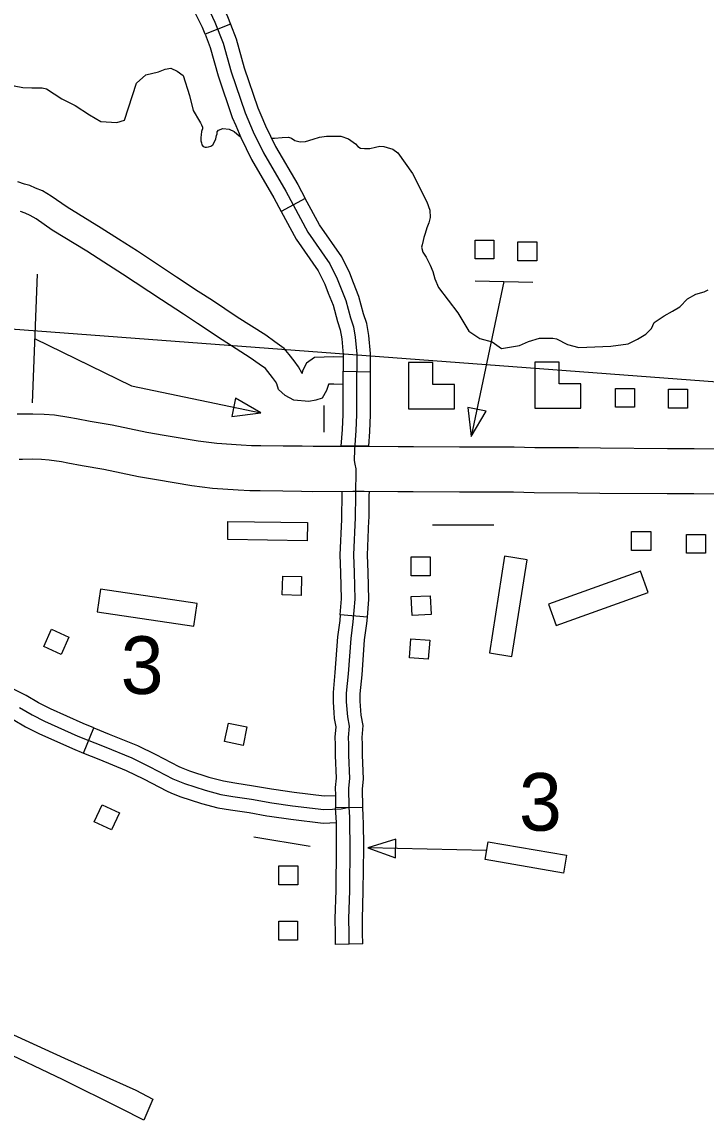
# Model space of a CAD drawing. Extents: x 61396 to 64680, y 55472 to 57605.
# Drawn here: x 62308.8 to 62426.4, y 55934.9 to 56123.6 of the extents above; entities that cross this region are included whole.
import ezdxf

# ---------------------------------------------------------------- set-up
doc = ezdxf.new("R2010")
doc.units = 0
for name, color, linetype in [('15', 7, 'Continuous'), ('31', 7, 'Continuous'), ('35', 7, 'Continuous'), ('46', 7, 'Continuous'), ('56', 7, 'Continuous'), ('57', 7, 'Continuous'), ('58', 7, 'Continuous'), ('Default', 7, 'Continuous')]:
    doc.layers.add(name, color=color, linetype=linetype)

msp = doc.modelspace()

# ---------------------------------------------------------------- linework, layer by layer
at = {"layer": '15'}
for points in [[(62308.01, 56056.27), (62308.83, 56056.27), (62310.69, 56056.29), (62312.62, 56056.26), (62314.42, 56056.09), (62316.89, 56055.73), (62318.17, 56055.48), (62320.53, 56055.04), (62324.31, 56054.42), (62330.3, 56053.15), (62333.27, 56052.65), (62339.11, 56051.65), (62342.29, 56051.27), (62346.52, 56050.99), (62348.3, 56050.87), (62349.88, 56050.85), (62353.73, 56050.8), (62356.99, 56050.77), (62358.87, 56050.72), (62365.66, 56050.75), (62367.7, 56050.75), (62373.52, 56050.7), (62376.13, 56050.67), (62384.04, 56050.62), (62387.49, 56050.64), (62393.45, 56050.64), (62397.02, 56050.52), (62404.49, 56050.49), (62408.26, 56050.42), (62419.8, 56050.34), (62424.38, 56050.34), (62432.67, 56050.29)], [(62432.65, 56042.48), (62424.35, 56042.53), (62419.77, 56042.53), (62408.16, 56042.6), (62404.4, 56042.68), (62396.86, 56042.71), (62393.31, 56042.83), (62387.51, 56042.83), (62384.04, 56042.81), (62376.07, 56042.86), (62373.45, 56042.88), (62367.66, 56042.93), (62365.68, 56042.93), (62358.78, 56042.91), (62356.85, 56042.96), (62353.65, 56042.99), (62349.77, 56043.04), (62347.98, 56043.06), (62346, 56043.2), (62341.58, 56043.48), (62337.99, 56043.91), (62331.97, 56044.95), (62328.84, 56045.47), (62322.87, 56046.74), (62319.17, 56047.34), (62316.7, 56047.81), (62315.59, 56048.02), (62313.48, 56048.33), (62312.18, 56048.46), (62310.69, 56048.48), (62308.89, 56048.45), (62308.33, 56048.45)]]:
    msp.add_lwpolyline(points, dxfattribs=at)
at = {"layer": '31'}
for p, q in [((62344.65, 56123.22), (62340.29, 56121.51)), ((62357.51, 56093.28), (62353.38, 56091.07)), ((62364.06, 56063.61), (62368.75, 56063.53)), ((62368.43, 56050.74), (62363.72, 56050.74)), ((62368.2, 56021.36), (62363.53, 56021.76)), ((62319.42, 55997.99), (62321.17, 56002.34)), ((62362.74, 55988.63), (62367.43, 55988.72)), ((62367.43, 55988.72), (62367.43, 55988.72)), ((62367.42, 55965.2), (62362.73, 55965.13))]:
    msp.add_line(p, q, dxfattribs=at)
for points in [[(62333.64, 56136.67), (62338.22, 56132.83), (62341.42, 56129.46), (62342.2, 56128.31), (62342.87, 56127.15), (62344.13, 56124.56), (62344.65, 56123.22)], [(62340.29, 56121.51), (62339.83, 56122.69), (62338.73, 56124.95), (62338.23, 56125.81), (62337.76, 56126.51), (62335.01, 56129.41), (62330.63, 56133.08)], [(62340.8, 56126.05), (62341.98, 56123.62), (62343.4, 56119.98), (62344.78, 56115.08), (62347.17, 56108.04), (62348.56, 56104.77), (62350.36, 56101.12), (62354.17, 56094.55), (62357.94, 56087.51), (62361.76, 56082.06), (62363.01, 56079.51), (62364.52, 56075.74), (62365.32, 56072.8), (62365.82, 56071.25), (62366.11, 56069.45), (62366.36, 56066.56), (62366.41, 56063.57)], [(62344.65, 56123.22), (62345.63, 56120.72), (62347.02, 56115.77), (62349.37, 56108.87), (62349.88, 56107.65)], [(62340.29, 56121.51), (62341.18, 56119.23), (62342.55, 56114.38), (62344.98, 56107.2), (62345.56, 56105.83)], [(62349.88, 56107.65), (62350.69, 56105.75), (62352.42, 56102.23), (62356.22, 56095.69), (62357.51, 56093.28)], [(62345.56, 56105.83), (62346.42, 56103.79), (62348.29, 56100.02), (62352.12, 56093.41), (62353.38, 56091.07)], [(62365.82, 56078.79), (62365.16, 56080.46), (62363.78, 56083.26), (62359.94, 56088.74), (62357.51, 56093.28)], [(62353.38, 56091.07), (62355.94, 56086.28), (62359.73, 56080.87), (62360.87, 56078.55), (62361.47, 56077.05)], [(62368.75, 56063.53), (62368.71, 56066.68), (62368.44, 56069.74), (62368.1, 56071.81), (62367.56, 56073.47), (62366.75, 56076.48), (62365.82, 56078.79)], [(62361.47, 56077.05), (62362.29, 56074.99), (62363.07, 56072.13), (62363.54, 56070.7), (62363.79, 56069.16), (62364.02, 56066.44), (62364.06, 56063.61)], [(62363.72, 56050.74), (62363.95, 56053.57), (62364.06, 56056.15), (62364.02, 56058), (62364.02, 56061.16), (62364.06, 56063.33), (62364.06, 56063.61)], [(62366.29, 56046.84), (62366.1, 56047.65), (62366.03, 56047.94), (62365.99, 56048.33), (62366.02, 56050.11), (62366.29, 56053.42), (62366.4, 56056.12), (62366.37, 56058.03), (62366.37, 56061.14), (62366.41, 56063.57)], [(62368.43, 56050.74), (62368.63, 56053.28), (62368.75, 56056.1), (62368.71, 56058.05), (62368.71, 56061.12), (62368.75, 56063.25), (62368.75, 56063.53)], [(62365.08, 55988.68), (62365.02, 55991.95), (62365.21, 55993.62), (62365.02, 55997.64), (62365.02, 55999.5), (62364.97, 56000.69), (62365.11, 56002.6), (62364.82, 56004.23), (62364.63, 56006.81), (62364.63, 56008.29), (62364.97, 56011.64), (62365.4, 56017.7), (62365.78, 56020.52), (62366.11, 56024.44), (62365.97, 56029.03), (62365.88, 56032.04), (62366.14, 56038.47), (62366.19, 56042.27), (62366.29, 56046.84)], [(62363.78, 56038.14), (62363.8, 56038.53), (62363.84, 56042.31), (62363.86, 56042.93)], [(62368.46, 56037.94), (62368.48, 56038.4), (62368.53, 56042.22), (62368.55, 56042.93)], [(62363.53, 56021.76), (62363.77, 56024.51), (62363.63, 56028.96), (62363.53, 56032.05), (62363.78, 56038.14)], [(62368.2, 56021.36), (62368.46, 56024.38), (62368.31, 56029.1), (62368.22, 56032.03), (62368.46, 56037.94)], [(62363.53, 56021.76), (62363.45, 56020.78), (62363.07, 56017.95), (62362.63, 56011.84), (62362.29, 56008.41), (62362.29, 56006.72), (62362.42, 56004.95)], [(62367.1, 56005.3), (62366.98, 56006.9), (62366.98, 56008.17), (62367.3, 56011.44), (62367.73, 56017.46), (62368.11, 56020.27), (62368.2, 56021.36)], [(62321.17, 56002.34), (62319.35, 56003.07), (62313.72, 56005.61), (62311.67, 56006.65), (62309.54, 56007.89), (62307.27, 56009.04), (62306.42, 56009.43)], [(62304.46, 56005.17), (62305.24, 56004.82), (62307.29, 56003.78), (62309.43, 56002.53), (62311.7, 56001.38), (62317.51, 55998.76), (62319.42, 55997.99)], [(62308.41, 56005.84), (62310.55, 56004.59), (62312.71, 56003.49), (62318.43, 56000.92), (62322.93, 55999.1), (62327.69, 55997.15), (62330.77, 55995.66), (62334.77, 55993.58), (62336.78, 55992.75), (62340.31, 55991.6), (62342.99, 55990.9), (62345.05, 55990.56), (62348.25, 55990.07), (62351.76, 55989.47), (62355.33, 55988.95), (62360.69, 55988.3), (62363.69, 55988.41), (62365.08, 55988.68)], [(62362.42, 56004.95), (62362.5, 56003.94), (62362.75, 56002.49), (62362.62, 56000.73), (62362.67, 55999.45), (62362.67, 55997.58), (62362.86, 55993.7), (62362.67, 55992.06), (62362.7, 55990.72)], [(62367.43, 55988.72), (62367.36, 55991.84), (62367.56, 55993.54), (62367.36, 55997.69), (62367.36, 55999.55), (62367.32, 56000.65), (62367.47, 56002.72), (62367.15, 56004.52), (62367.1, 56005.3)], [(62321.17, 56002.34), (62323.82, 56001.27), (62328.65, 55999.29), (62331.82, 55997.76), (62335.76, 55995.71), (62336.21, 55995.52)], [(62319.42, 55997.99), (62322.05, 55996.93), (62326.74, 55995), (62329.72, 55993.57), (62333.78, 55991.46), (62334.41, 55991.19)], [(62336.21, 55995.52), (62337.59, 55994.95), (62340.97, 55993.85), (62343.48, 55993.2), (62345.42, 55992.88), (62348.63, 55992.38), (62351.7, 55991.86)], [(62351.7, 55991.86), (62352.13, 55991.79), (62355.64, 55991.27), (62360.79, 55990.65), (62362.7, 55990.72)], [(62334.41, 55991.19), (62335.96, 55990.55), (62339.66, 55989.35), (62342.51, 55988.61), (62344.68, 55988.25), (62347.88, 55987.76), (62350.92, 55987.24)], [(62362.7, 55990.72), (62362.74, 55988.63)], [(62362.87, 55986.04), (62362.82, 55986.9), (62362.74, 55988.57)], [(62365.08, 55965.17), (62365.05, 55967.03), (62365.02, 55969.49), (62365.16, 55974.36), (62365.24, 55982.03), (62365.21, 55985.89), (62365.16, 55987.01), (62365.08, 55988.68)], [(62367.58, 55981.64), (62367.58, 55982.02), (62367.56, 55985.95), (62367.5, 55987.12), (62367.42, 55988.78)], [(62350.92, 55987.24), (62351.4, 55987.16), (62355.02, 55986.63), (62360.59, 55985.95), (62362.87, 55986.04)], [(62362.89, 55981.69), (62362.9, 55982.03), (62362.87, 55986.04)], [(62362.73, 55965.13), (62362.7, 55967), (62362.68, 55969.51), (62362.81, 55974.41), (62362.89, 55981.69)], [(62367.42, 55965.2), (62367.39, 55967.06), (62367.36, 55969.47), (62367.5, 55974.32), (62367.58, 55981.64)]]:
    msp.add_lwpolyline(points, dxfattribs=at)
at = {"layer": '35'}
for points in [[(62299.41, 56123.93), (62299.41, 56123.04), (62298.76, 56122.51), (62297.74, 56122.47), (62296.6, 56122.47), (62295.71, 56122.06), (62295.26, 56121.37), (62295.43, 56120.07), (62295.75, 56117.96), (62296.69, 56117.35), (62298.43, 56116.99), (62300.18, 56115.93), (62301.68, 56115.69), (62303.14, 56114.39), (62305.09, 56113.53), (62306.27, 56113.09), (62307.45, 56112.64), (62308.95, 56112.36), (62310.49, 56112.28), (62312.28, 56112.32), (62313.05, 56112.15)], [(62313.05, 56112.15), (62315.64, 56110.41), (62317.98, 56109.3), (62320.44, 56107.65), (62322.38, 56106.52), (62325.14, 56106.35), (62326.47, 56106.75), (62328.51, 56113.11), (62330.09, 56114.52), (62332.28, 56115.07), (62333.46, 56115.54), (62334.41, 56115.7), (62335.5, 56115.15), (62336.53, 56114.44), (62337.63, 56110.99), (62338.25, 56108.4), (62339.36, 56106.59), (62339.52, 56106.31), (62339.69, 56105.94), (62339.83, 56105.54), (62339.84, 56105.29), (62339.75, 56104.97), (62339.66, 56104.78), (62339.65, 56104.21), (62339.57, 56103.8), (62339.59, 56103.21), (62339.66, 56102.83), (62339.73, 56102.52), (62339.99, 56102.25), (62340.31, 56102.13), (62340.56, 56102.14)], [(62340.56, 56102.14), (62340.9, 56102.15), (62341.31, 56102.29), (62341.61, 56102.49), (62341.91, 56103.03), (62342.14, 56103.54), (62342.25, 56104.14), (62342.37, 56104.43), (62342.39, 56104.74), (62342.6, 56105.06), (62343.34, 56105.3), (62344.41, 56105.21), (62345.27, 56104.83), (62346.14, 56104.04), (62346.32, 56103.97)], [(62351.76, 56103.65), (62352.23, 56103.67), (62353.57, 56103.75), (62354.63, 56103.81), (62355.17, 56103.67), (62355.72, 56103.25), (62356.66, 56103.03), (62357.54, 56103.09), (62358.9, 56103.51), (62359.96, 56103.83), (62361.17, 56104.02), (62363.65, 56104.01), (62364.95, 56103.55), (62366.13, 56102.71), (62366.55, 56102.22), (62367, 56101.95), (62367.69, 56101.88), (62368.6, 56101.87), (62369.6, 56102.09), (62370.37, 56102.28), (62371.03, 56102.2), (62371.63, 56102.03), (62372.55, 56101.78), (62373.41, 56101.15), (62375.97, 56097.56), (62378.4, 56092.74), (62378.91, 56091.31), (62378.99, 56090), (62378.76, 56089.11), (62378.44, 56088.25), (62378.13, 56087.27), (62377.93, 56086.61), (62377.79, 56086.07), (62377.6, 56085.31), (62377.51, 56084.93), (62377.73, 56084.09), (62378.32, 56083.2), (62378.99, 56081.81), (62379.43, 56080.75), (62379.78, 56079.51), (62380.42, 56078.02), (62383.76, 56073.63), (62385.66, 56070.48), (62387.52, 56069.22), (62389.67, 56068.67), (62391.28, 56067.52), (62394.38, 56068.04), (62395.89, 56068.7), (62397.79, 56069.27), (62400.07, 56069.27), (62400.73, 56069.18), (62402.63, 56068.23), (62404.53, 56067.66), (62410.03, 56067.94), (62413.04, 56068.3), (62414.67, 56069.14), (62416.06, 56070), (62417.06, 56070.97), (62417.53, 56071.96), (62419.22, 56073.14), (62420.64, 56073.91), (62421.9, 56074.67)], [(62421.9, 56074.67), (62423.23, 56076.06), (62424.65, 56076.86), (62426.11, 56077.28), (62426.82, 56077.62)]]:
    msp.add_lwpolyline(points, dxfattribs=at)
at = {"layer": '46'}
for points in [[(62364.03, 56066.02), (62362.44, 56066.1), (62359.1, 56065.99), (62357.76, 56064.99), (62357.04, 56063.67), (62357, 56063.23), (62356.97, 56063.23), (62356.37, 56064.38), (62355.6, 56065.4), (62354.75, 56066.47), (62353.91, 56067.54), (62352.3, 56068.64), (62350.72, 56069.79), (62345.82, 56072.92), (62341.58, 56075.77), (62339.1, 56077.33), (62335.39, 56079.78), (62328.67, 56084.24), (62325.43, 56086.3), (62322.43, 56088.2), (62316.57, 56091.78), (62313.81, 56093.7), (62312.37, 56094.59), (62311.15, 56095.08), (62310.18, 56095.5), (62309.25, 56095.78), (62308.1, 56096.16)], [(62364.03, 56061.33), (62362.41, 56061.41), (62361.51, 56061.38), (62361.51, 56061.31), (62361.2, 56060.3), (62360.45, 56059.01), (62359.32, 56058.63), (62358.12, 56058.41), (62355.54, 56058.65), (62354.07, 56059.43), (62352.92, 56060.48), (62352.62, 56061.43), (62352.39, 56061.87), (62351.9, 56062.53), (62351.08, 56063.55), (62350.67, 56064.07), (62349.59, 56064.81), (62348.07, 56065.92), (62343.25, 56069), (62339.02, 56071.84), (62336.56, 56073.39), (62332.81, 56075.88), (62326.12, 56080.31), (62322.91, 56082.35), (62319.96, 56084.22), (62314, 56087.85), (62311.23, 56089.78), (62310.24, 56090.39), (62309.36, 56090.75), (62308.58, 56091.08)]]:
    msp.add_lwpolyline(points, dxfattribs=at)
at = {"layer": '56'}
for points in [[(62386.71, 56082.9), (62386.71, 56086.15), (62389.97, 56086.15), (62389.97, 56082.9)], [(62394.06, 56082.57), (62394.06, 56085.82), (62397.32, 56085.82), (62397.32, 56082.57)], [(62410.87, 56057.42), (62410.87, 56060.67), (62414.13, 56060.67), (62414.13, 56057.42)], [(62419.96, 56057.26), (62419.96, 56060.51), (62423.22, 56060.51), (62423.22, 56057.26)], [(62388.62, 56056.73), (62385.5, 56057.38), (62386.07, 56052.38)], [(62344.18, 56034.67), (62344.22, 56037.79), (62357.89, 56037.59), (62357.85, 56034.47)], [(62413.64, 56032.8), (62413.64, 56036.05), (62416.91, 56036.05), (62416.91, 56032.8)], [(62423.08, 56032.32), (62423.08, 56035.57), (62426.34, 56035.57), (62426.34, 56032.32)], [(62375.72, 56028.46), (62375.72, 56031.71), (62378.99, 56031.71), (62378.99, 56028.46)], [(62353.57, 56025.17), (62353.64, 56028.42), (62356.9, 56028.35), (62356.83, 56025.1)], [(62375.88, 56021.66), (62375.75, 56024.91), (62379.01, 56025.04), (62379.14, 56021.79)], [(62312.56, 56016.29), (62313.88, 56019.26), (62316.86, 56017.94), (62315.54, 56014.96)], [(62375.43, 56014.39), (62375.69, 56017.64), (62378.94, 56017.37), (62378.68, 56014.13)], [(62343.64, 55999.98), (62344.31, 56003.16), (62347.5, 56002.49), (62346.84, 55999.31)], [(62321.24, 55986.18), (62322.63, 55989.11), (62325.58, 55987.71), (62324.18, 55984.78)], [(62373.05, 55979.99), (62373.12, 55983.18), (62368.3, 55981.69)], [(62388.43, 55979.69), (62388.96, 55982.77), (62402.43, 55980.45), (62401.9, 55977.37)], [(62352.96, 55975.36), (62352.96, 55978.61), (62356.22, 55978.61), (62356.22, 55975.36)], [(62352.95, 55965.85), (62352.95, 55969.1), (62356.21, 55969.1), (62356.21, 55965.85)]]:
    msp.add_lwpolyline(points, close=True, dxfattribs=at)
for points in [[(62391.69, 56079.02), (62386.07, 56052.38)], [(62386.76, 56079.13), (62396.62, 56078.9)], [(62379.38, 56037.23), (62389.94, 56037.23)], [(62348.67, 55983.61), (62358.34, 55982.02)], [(62388.69, 55981.23), (62368.3, 55981.69)]]:
    msp.add_lwpolyline(points, dxfattribs=at)
at = {"layer": '57'}
for p, q in [((62391.8, 56031.81), (62389.18, 56015.22)), ((62395.66, 56031.2), (62391.8, 56031.81)), ((62393.04, 56014.61), (62395.66, 56031.2)), ((62415.14, 56029.27), (62399.33, 56023.59)), ((62416.46, 56025.59), (62415.14, 56029.27)), ((62322.29, 56026.14), (62321.72, 56022.28)), ((62338.91, 56023.7), (62322.29, 56026.14)), ((62400.65, 56019.92), (62416.46, 56025.59)), ((62321.72, 56022.28), (62338.34, 56019.83)), ((62338.34, 56019.83), (62338.91, 56023.7)), ((62399.33, 56023.59), (62400.65, 56019.92)), ((62389.18, 56015.22), (62393.04, 56014.61)), ((62300.7, 55952.65), (62316.12, 55945.56)), ((62315.92, 55941.84), (62300.26, 55949.28)), ((62316.12, 55945.56), (62328.4, 55940.08)), ((62325.81, 55936.94), (62315.92, 55941.84)), ((62328.4, 55940.08), (62331.34, 55938.51)), ((62331.34, 55938.51), (62329.77, 55934.94)), ((62329.77, 55934.94), (62325.81, 55936.94))]:
    msp.add_line(p, q, dxfattribs=at)
msp.add_lwpolyline([(62310.99, 56069.22), (62327.67, 56061.08), (62349.89, 56056.44)], dxfattribs=at)
msp.add_lwpolyline([(62345.53, 56058.98), (62344.88, 56055.86), (62349.89, 56056.44)], close=True, dxfattribs=at)
at = {"layer": '58'}
for points in [[(62311.45, 56080.27), (62310.54, 56058.16)], [(62360.69, 56057.71), (62360.69, 56053.15)]]:
    msp.add_lwpolyline(points, dxfattribs=at)
for points in [[(62375.25, 56057.15), (62383.19, 56057.15), (62383.19, 56061.34), (62379.44, 56061.34), (62379.44, 56065.09), (62375.25, 56065.09)], [(62396.98, 56057.25), (62404.91, 56057.25), (62404.91, 56061.44), (62401.16, 56061.44), (62401.16, 56065.19), (62396.98, 56065.19)]]:
    msp.add_lwpolyline(points, close=True, dxfattribs=at)
at = {"layer": 'Default'}
msp.add_line((62028.43, 56091.83), (62651.44, 56045.01), dxfattribs=at)

# ---------------------------------------------------------------- texts
at = {"layer": '56'}
msp.add_text('3', height=9.9, dxfattribs=at).set_placement((62394.27, 55984.66))
at = {"layer": '57'}
msp.add_text('3', height=9.9, dxfattribs=at).set_placement((62325.79, 56008.16))

doc.saveas('drawing.dxf')
